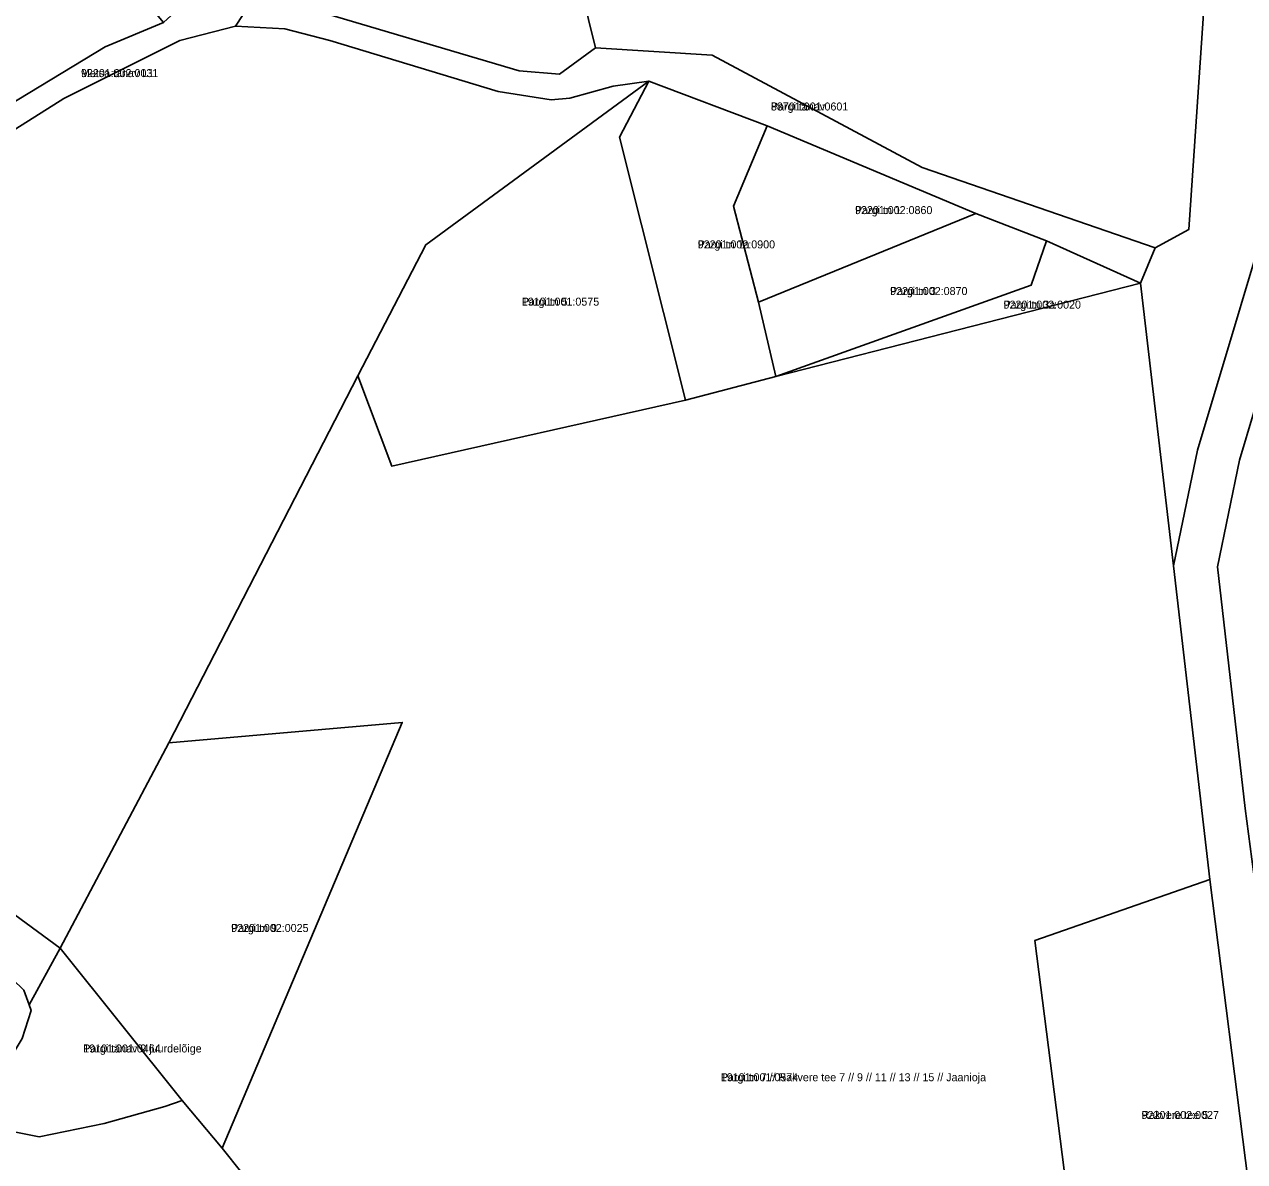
# Model space of a CAD drawing. Extents: x 601493 to 643081, y 6584980 to 6634019.
# Drawn here: x 611108.4 to 611337.1, y 6605713.4 to 6605926.7 of the extents above; entities that cross this region are included whole.
import ezdxf

# ---------------------------------------------------------------- set-up
doc = ezdxf.new("R2010")
doc.units = 0
for name, color, linetype in [('L_AADRESS', 7, 'Continuous'), ('PIIR', 7, 'Continuous'), ('TUNNUS', 7, 'Continuous')]:
    doc.layers.add(name, color=color, linetype=linetype)

msp = doc.modelspace()

# ---------------------------------------------------------------- linework, layer by layer
at = {"layer": 'PIIR'}
for points in [[(611337.83, 6605709.71), (611330.64, 6605766.3), (611323.81, 6605825.14), (611328.28, 6605846.84), (611344.47, 6605900.82), (611362.28, 6605937.88), (611378.18, 6605962.48), (611398.78, 6605987.53), (611414.13, 6606005.82), (611439.42, 6606040.22), (611444.21, 6606055.49), (611458.7, 6606092.46), (611464.22, 6606109.01), (611470.66, 6606126.5), (611478.3, 6606147.34), (611492.69, 6606186.99), (611510.31, 6606229.52), (611517.5, 6606249.21), (611514.95, 6606250.23), (611537.9, 6606308.8)], [(611330.06, 6605937.96), (611326.67, 6605888.22), (611320.38, 6605884.78), (611276.69, 6605899.86), (611237.35, 6605920.93), (611215.46, 6605922.32), (611207.62, 6605953.98)], [(611163.89, 6605692.8), (611145.44, 6605715.95), (611179.22, 6605795.77), (611135.45, 6605791.96), (611170.92, 6605860.77), (611177.25, 6605843.85), (611232.35, 6605856.2), (611249.28, 6605860.65), (611317.63, 6605878.14), (611323.81, 6605825.14), (611330.64, 6605766.3), (611297.82, 6605754.91), (611304.77, 6605700.57)], [(611338.86, 6605853.96), (611336.16, 6605844.98), (611332.06, 6605824.97), (611337.21, 6605779.66)], [(611108.3, 6605745.6), (611109.3, 6605742.79), (611109.68, 6605741.73), (611107.99, 6605736.53)], [(611104.89, 6605719.31), (611111.18, 6605718.07), (611123.34, 6605720.54), (611134.69, 6605723.74), (611137.98, 6605724.9), (611145.44, 6605715.95), (611163.89, 6605692.8), (611151.29, 6605694.73), (611113.89, 6605688.79), (611084.63, 6605677.04)]]:
    msp.add_lwpolyline(points, dxfattribs=at)
for points in [[(611398.2, 6605988.02), (611398.78, 6605987.53), (611378.18, 6605962.48), (611362.28, 6605937.88), (611344.47, 6605900.82), (611328.28, 6605846.84), (611323.81, 6605825.14), (611317.63, 6605878.14), (611320.38, 6605884.78), (611326.67, 6605888.22), (611330.06, 6605937.96), (611339.17, 6605941.28), (611353.74, 6605933.06)], [(611009.76, 6605850.83), (611062.06, 6605884.88), (611062.56, 6605888.3), (611027.99, 6605894.63), (611011.92, 6605894.26), (611012.29, 6605899.01), (611022.49, 6605900.98), (611051.97, 6605895.45), (611070.25, 6605889.12), (611088.7, 6605901.38), (611123.51, 6605922.45), (611134.49, 6605927.03), (611165.05, 6605954.92), (611179.05, 6605967.82), (611186.58, 6605975.54), (611199.99, 6605983.63), (611201.01, 6605979.17), (611192.29, 6605975.95), (611158.84, 6605942.95), (611147.96, 6605926.34), (611137.5, 6605923.67), (611115.81, 6605912.81), (611082.29, 6605891.66), (611013.55, 6605849.98)], [(611110.08, 6605958.56), (611117.01, 6605949.26), (611120.11, 6605944.23), (611134.49, 6605927.03), (611123.51, 6605922.45), (611088.7, 6605901.38), (611081.69, 6605912.32), (611074.1, 6605924.42), (611080.7, 6605923.59), (611085.81, 6605925.29), (611092.15, 6605928.73), (611097.93, 6605934.81), (611102.16, 6605942.64), (611105.98, 6605952.13), (611107.25, 6605954.76), (611107.28, 6605954.8)], [(611207.62, 6605953.98), (611215.46, 6605922.32), (611208.71, 6605917.32), (611201.16, 6605917.95), (611163.79, 6605929.05), (611161.61, 6605935.68), (611185.83, 6605946.35), (611190.69, 6605948.32)], [(611147.96, 6605926.34), (611158.84, 6605942.95), (611161.61, 6605935.68), (611163.79, 6605929.05), (611201.16, 6605917.95), (611208.71, 6605917.32), (611215.46, 6605922.32), (611237.35, 6605920.93), (611276.69, 6605899.86), (611320.38, 6605884.78), (611317.63, 6605878.14), (611300, 6605886.11), (611286.78, 6605891.22), (611247.61, 6605907.64), (611225.45, 6605916.03), (611218.77, 6605915.13), (611210.66, 6605912.84), (611207.12, 6605912.54), (611197.19, 6605914.12), (611165.66, 6605923.69), (611157.22, 6605925.86)], [(611039.07, 6605812.36), (611001.4, 6605788.06), (610929.47, 6605759.72), (610910.09, 6605783.32), (610921.07, 6605788.83), (610931.04, 6605795.1), (611013.55, 6605849.98), (611082.29, 6605891.66), (611115.81, 6605912.81), (611137.5, 6605923.67), (611147.96, 6605926.34), (611157.22, 6605925.86), (611165.66, 6605923.69), (611197.19, 6605914.12), (611207.12, 6605912.54), (611210.66, 6605912.84), (611218.77, 6605915.13), (611225.45, 6605916.03), (611183.62, 6605885.37), (611170.92, 6605860.77), (611135.45, 6605791.96), (611115.08, 6605753.45), (611094.98, 6605768.18), (611075.19, 6605763.83)], [(611177.25, 6605843.85), (611170.92, 6605860.77), (611183.62, 6605885.37), (611225.45, 6605916.03), (611219.94, 6605905.53), (611232.35, 6605856.2)], [(611219.94, 6605905.53), (611225.45, 6605916.03), (611247.61, 6605907.64), (611241.33, 6605892.58), (611245.99, 6605874.57), (611249.28, 6605860.65), (611232.35, 6605856.2)], [(611286.78, 6605891.22), (611245.99, 6605874.57), (611241.33, 6605892.58), (611247.61, 6605907.64)], [(611245.99, 6605874.57), (611286.78, 6605891.22), (611300, 6605886.11), (611297.13, 6605877.76), (611249.28, 6605860.65)], [(611249.28, 6605860.65), (611297.13, 6605877.76), (611300, 6605886.11), (611317.63, 6605878.14)], [(611338.86, 6605853.96), (611340.9, 6605853.58), (611341.65, 6605813.73), (611343.53, 6605769.75), (611343.83, 6605762.99), (611345.01, 6605742.6), (611345.67, 6605715.51), (611337.21, 6605779.66), (611332.06, 6605824.97), (611336.16, 6605844.98)], [(611115.08, 6605753.45), (611135.45, 6605791.96), (611179.22, 6605795.77), (611145.44, 6605715.95), (611137.98, 6605724.9)], [(611066.24, 6605748.39), (611075.19, 6605763.83), (611094.98, 6605768.18), (611115.08, 6605753.45), (611109.3, 6605742.79), (611108.3, 6605745.6), (611104.08, 6605749.62), (611099.34, 6605749.21), (611094.9, 6605743.54), (611088.81, 6605738.7), (611081.8, 6605737.05), (611075.31, 6605739.32), (611068.3, 6605744.06)], [(611297.82, 6605754.91), (611330.64, 6605766.3), (611337.83, 6605709.71), (611337.74, 6605708.73), (611335.72, 6605685.29), (611334.14, 6605666.68), (611332.69, 6605652.37), (611332.15, 6605653.72), (611326.39, 6605667.02), (611324.33, 6605675.06), (611319.79, 6605679.92), (611306.51, 6605686.97), (611304.77, 6605700.57)], [(611137.98, 6605724.9), (611134.69, 6605723.74), (611123.34, 6605720.54), (611111.18, 6605718.07), (611104.89, 6605719.31), (611101.07, 6605723.54), (611100.87, 6605727.66), (611105.31, 6605731.99), (611107.99, 6605736.53), (611109.68, 6605741.73), (611109.3, 6605742.79), (611115.08, 6605753.45)]]:
    msp.add_lwpolyline(points, close=True, dxfattribs=at)

# ---------------------------------------------------------------- texts
at = {"layer": 'L_AADRESS'}
for s, p in [('Metsa tänav L1', (611118.99, 6605916.8)), ('Pargi tänav', (611248.34, 6605910.54)), ('Pargi tn 1', (611264.1, 6605891.11)), ('Pargi tn 1a', (611234.61, 6605884.68)), ('Pargi tn 5', (611201.64, 6605873.94)), ('Pargi tn 3', (611270.68, 6605875.93)), ('Pargi tn 3a', (611291.95, 6605873.38)), ('Pargi tn 9', (611147.15, 6605756.48)), ('Pargi tänav 9 juurdelõige', (611119.42, 6605733.89)), ('Pargi tn 7 // Rakvere tee 7 // 9 // 11 // 13 // 15 // Jaanioja', (611238.94, 6605728.49)), ('Rakvere tee 5', (611317.82, 6605721.41))]:
    msp.add_text(s, height=1.5, dxfattribs=at).set_placement(p)
at = {"layer": 'TUNNUS'}
for s, p in [('92201:002:0031', (611118.99, 6605916.8)), ('88701:001:0601', (611248.34, 6605910.54)), ('92201:002:0860', (611264.1, 6605891.11)), ('92201:002:0900', (611234.61, 6605884.68)), ('19101:001:0575', (611201.64, 6605873.94)), ('92201:002:0870', (611270.68, 6605875.93)), ('92201:002:0020', (611291.95, 6605873.38)), ('92201:002:0025', (611147.15, 6605756.48)), ('19101:001:0464', (611119.42, 6605733.89)), ('19101:001:0574', (611238.94, 6605728.49)), ('92201:002:0027', (611317.82, 6605721.41))]:
    msp.add_text(s, height=1.5, dxfattribs=at).set_placement(p)

doc.saveas('drawing.dxf')
